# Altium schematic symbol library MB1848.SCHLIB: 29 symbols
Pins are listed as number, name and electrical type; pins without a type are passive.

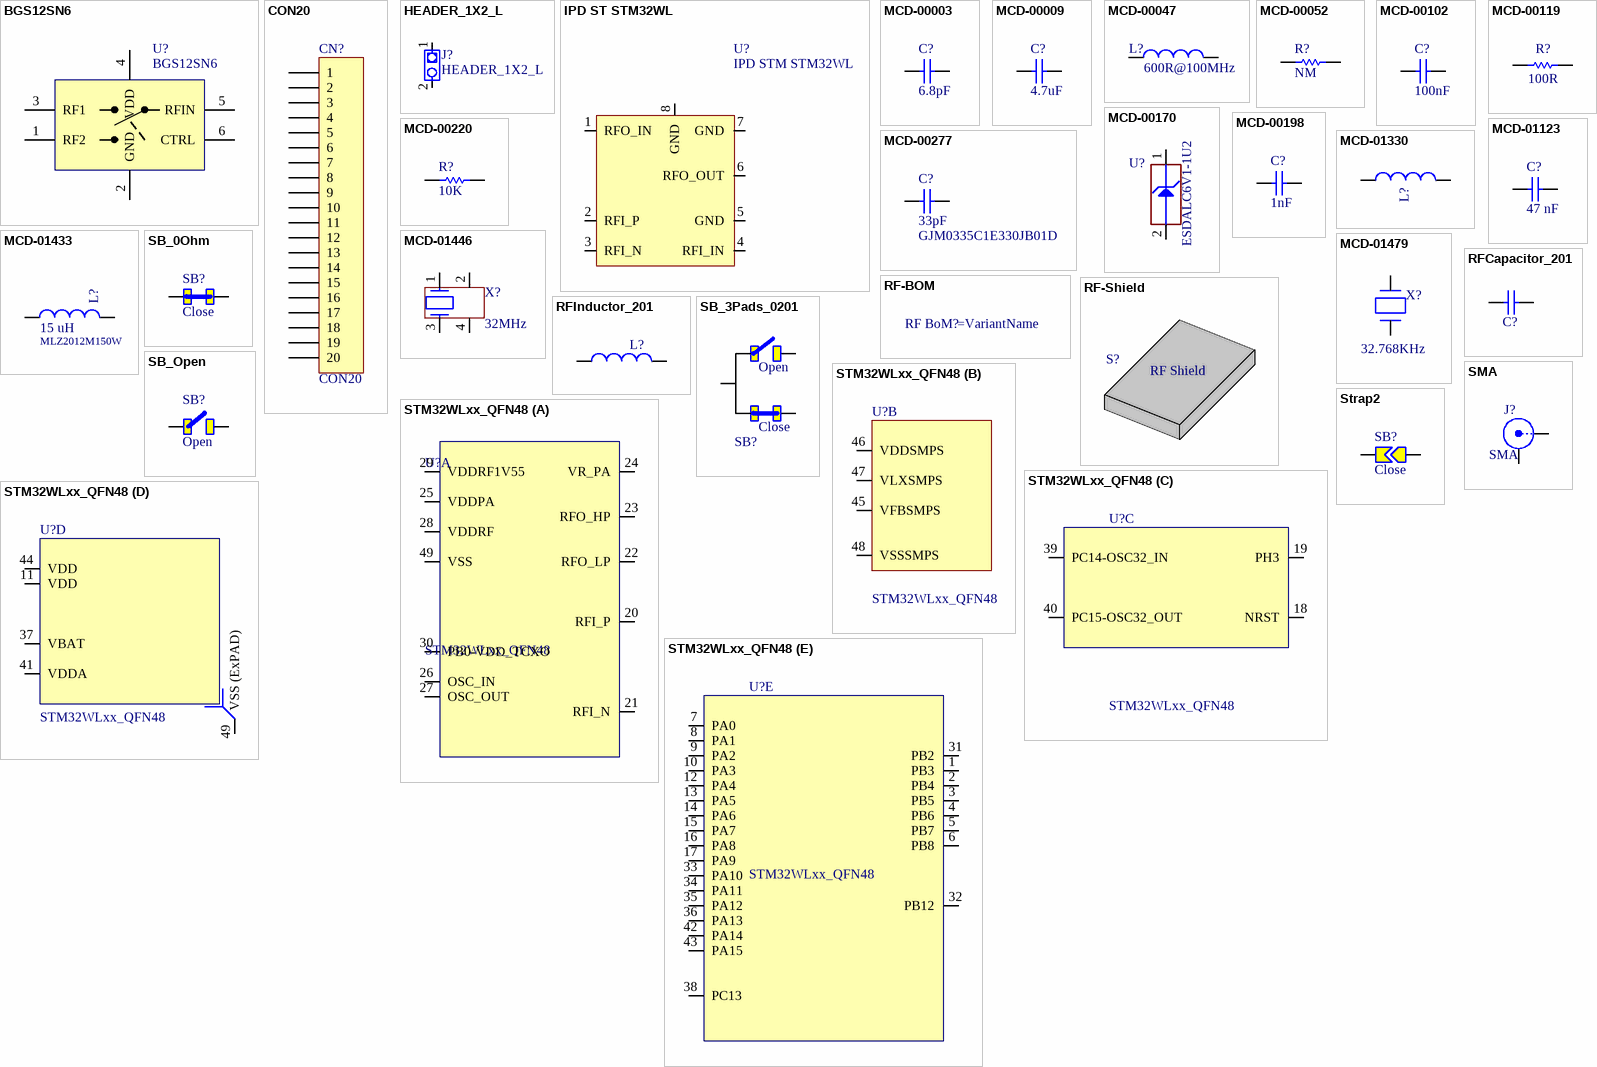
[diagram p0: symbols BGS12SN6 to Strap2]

## BGS12SN6
designator U?
DC switch - Ultra-Low  SPDT analog switch; Manufacturer: INFINEON
footprint SON40P70X40-6N (SON, 6-Leads, Body 1.10x0.70mm, Pitch 0.40mm)
footprint TSNP-6-2 (TSNP-6-2; Body 1.1 x 0.7 mm (LxW typ))
pins: 1 RF2, 2 GND, 3 RF1, 4 VDD, 5 RFIN, 6 CTRL

## CON20
designator CN?
Connector right-angle, pitch 2.54mm, 20 contacts; Manufacturer: SAMTEC; Manufacturer_Part_Number: TSW-120-07-L-S
footprint CO_SAMTEC_TSW-120-07-x-S (Header, 20-Leads, 50.80x2.54x10.80mm, Pitch 2.54mm)
pins: 1, 2, 3, 4, 5, 6, 7, 8, 9, 10, 11, 12, 13, 14, 15, 16, 17, 18, 19, 20

## HEADER_1X2_L
designator J?
Manufacturer: MOLEX
footprint Header F 1x2x2.54 TH V (1x2x2.54 Header TH V Female)
footprint Header M 1x2x2.54 TH V (1x2x2.54 Header TH V Male)
footprint Header F 1x2x2.00 TH V (1x2x2.00 Header TH V Male height=5.5mm)
footprint Header F 1x2x2.00 TH V with Jumper (1x2x2.00 Header TH V Male height=5.5mm)
footprint Header NF 1x2x2.54 TH (1x2x2.54 Header TH Not Fitted)
footprint CO_MOLEX_22-03-2021
pins: 1, 2

## IPD ST STM32WL
designator U?, comment IPD STM STM32WL
Manufacturer: STMICROELECTRONICS
footprint IPD STM (IPD STM STM32WL, Body 2.20 x 1.90 x 0.710 mm (LxWxH max))
pins: 1 RFO_IN, 2 RFI_P, 3 RFI_N, 4 RFI_IN, 5 GND (power), 6 RFO_OUT, 7 GND, 8 GND

## MCD-00003
designator C?, comment value 6.8pF  (hidden comment: Capacitor)
Capacitor, MLCC, 6.8pF, 50V, NPO, +-0.1pF, 0402, T=0.5mm; Manufacturer_Part_Number: GRM1555C1H6R8BA01; Manufacturer: MURATA
footprint 0402
pins: 1, 2

## MCD-00009
designator C?  value 4.7uF
Capacitor, MLCC, 4.7uF, 16V, X5R, 10%, 0603, T=0.8mm; Manufacturer_Part_Number: CC0603KRX5R7BB475; Manufacturer: YAGEO
footprint CAPC1608X09N (Chip Capacitor, 2-Leads, Body 1.60x0.80x0.90mm (0603))
pins: 1, 2

## MCD-00047
designator L?  value 600R@100MHz
SMD Chip ferrite bead, 600R@100MHz +/-25%, 350mA, 500mohm DC, 0603, T=0.8mm; Manufacturer_Part_Number: BK1608HS601-T; Manufacturer: Taiyo Yuden
footprint INDC1608X95N (Chip Inductor, 2-Leads, Body 1.75x0.95x0.95mm (0603))
pins: 1, 2

## MCD-00052
designator R?, comment value NM  (hidden comment: Resistor)
Resistor,0R,0402,5%,1/16W; Internal_Part_Number: MCD-00052; Manufacturer_Part_Number: RC0402JR-070RL; Manufacturer: YAGEO; Provided_By: SUBCO; Initial_Board_Reference: MB1274
footprint R0402
pins: 1, 2

## MCD-00102
designator C?  value 100nF
Capacitor, MLCC, 100nF, 16V, X7R, 10%, 0402, T=0,5mm; Manufacturer_Part_Number: CC0402KRX7R7BB104; Manufacturer: YAGEO
footprint CAPC1005X06N
pins: 1, 2

## MCD-00119
designator R?  value 100R  (hidden comment: MCD-00119)
Thick Film Resistors - SMD 1/20watt 100ohms 5% 200ppm; Manufacturer_Part_Number: CRCW0201100RJNED; Manufacturer: Vishay / Dale
footprint RESC1005X04N (Chip Resistor, 2-Leads, Body 1.00x0.50mm (0402))
footprint 0201
pins: 1, 2

## MCD-00170
designator U?  Manufacturer_Part_Number: ESDALC6V1-1U2
ESD protection 6V1; Manufacturer: STMICROELECTRONICS
footprint DIOM0603X03N (Molded Diode, 2-Leads, Body 0.60x0.30mm)
pins: 1 IO1, 2 GND

## MCD-00198
designator C?  value 1nF  (hidden comment: MCD-00198)
Multilayer ceramic capacitors X7R ±10%, 50V; Manufacturer_Part_Number: GRM033R71H102KA12D; Manufacturer: MURATA
footprint CAPC1005X06N
footprint 0201
pins: 1, 2

## MCD-00220
designator R?  value 10K
Resistor,10K,0603,1%,1/10W; Manufacturer_Part_Number: RC0603FR-0710KL; Manufacturer: YAGEO
footprint RESC1608X05N (Chip Resistor, 2-Leads, Body 1.60x0.80mm (0603))
pins: 1, 2

## MCD-00277
designator C?  value 33pF  Manufacturer_Part_Number: GJM0335C1E330JB01D
Multilayer Ceramic Capacitors MLCC - SMD/SMT 0201 33pF 25volts C0G 5%; Manufacturer: MURATA
footprint 0402
footprint 0201
pins: 1, 2

## MCD-01123
designator C?  value 47 nF
Capacitor, MLCC,47nF, 16V, X7R, 10%, 0402, T=0.5mm; Manufacturer_Part_Number: GCM155R71E473KA55; Manufacturer: MURATA
footprint 0402
pins: 1, 2

## MCD-01330
designator L?  (value not drawn)
Inductor, 47nH, +-0.1nH, 140mA, 0402; Value: NC
footprint IND_MURATA_LQW15A (Inductor 2-Leads,Body 1.10x0.70x0.60mm(max))
pins: 1, 2

## MCD-01433
designator L?  value 15 uH  Manufacturer_Part_Number: MLZ2012M150W
MLZ2012 Multilayer Shielded Inductor 15 uH, ±5%; Manufacturer: TDK
footprint INDC2012X13N (Chip Inductor, 2-Leads, Body 2.0x1.2x1.3 (0805))
pins: 1, 2

## MCD-01446
designator X?  value 32MHz
Crystal 32 MHz, 8pF, -+10 PPM, R=60Ω, SMD; Manufacturer_Part_Number: NX2016SA 32MHz EXS00A-CS06465; Manufacturer: NDK
footprint OSC_NDK_NX2016SA (Crystal, 4-Leads, Body 2.10x1.61x0.50mm (max), Pitch 1.35x1.05mm)
signal-integrity model Guessed Model (IC Model Details Guessed by Setup Helper)
pins: 1, 2, 3, 4

## MCD-01479
designator X?, comment value 32.768KHz  (hidden comment: XTAL_2_PINS)
Crystal 32.768kHz, 6pF, -+20PPM, R=80K, SMD; Manufacturer_Part_Number: NX2012SA 32.768KHz EXS00A-MU00527; Manufacturer: NDK
footprint OSC_NDK_NX2012SA (Crystal, 2-Leads, Body 2.05x1.20x0.55mm (Tol:-/+0.05))
pins: 1 X1, 2 X2

## RF-BOM
designator RF BoM?  (value not drawn)  (mechanical)

## RF-Shield
designator S?  (value not drawn)  (mechanical)
RF Shield Frame + Cover without apertures; Manufacturer: Masach Tech; Manufacturer_Part_Number: MS409-10

## RFCapacitor_201
designator C?  (value not drawn)
RF Capacitor High-Q, 0201; Value: NC
footprint 0201
footprint rlc_201_smd
pins: 1, 2

## RFInductor_201
designator L?, comment Ferrite  (value not drawn)
Thick Film Resistor ±5%, 1/20W; Manufacturer_Part_Number: CRCW02010000Z0ED; Manufacturer: Vishay/Dale; Part_Type: Inductor; Value: 0R
footprint 0201
footprint rlc_201_smd
pins: 1, 2

## SB_0Ohm
designator SB?, comment Close
Solder Bridge 0R [0402] (Populated with 0 Ohm); Manufacturer: Vishay / Dale; Manufacturer_Part_Number: RCS04020000Z0ED; VALUE: 0
footprint SB_0402 (Souder Bridge [0402])
signal-integrity model Guessed Model (IC Model Details Guessed by Setup Helper)
pins: 1, 2

## SB_3Pads_0201
designator SB?, comment SB_3Pads  (value not drawn)
Solder Bridge
footprint SB3PADS_0201 (Solder Bridge 0 Ohm (0201))
pins: 1, 2, 3

## SB_Open
designator SB?, comment Open
Solder Bridge Open [0402] (Unpopulated)
footprint SB_0402 (Souder Bridge [0402])
signal-integrity model Guessed Model (IC Model Details Guessed by Setup Helper)
pins: 1, 2

## SMA
designator J?
SMA Straight Connector; Manufacturer: Johnson / Cinch Connectivity Solutions; Manufacturer_Part_Number: 142-0701-841
footprint SMA_end_launch_1.0mm_9.52mm (SMA end launch for 1.0mm PCB thickness; 9.52mm)
pins: 1 Signal "RF signal", 2 GND "Ground signal"

## STM32WLxx_QFN48
designator U?
STM32WL ARM MCU Multiprotocol LPWAN 32-bit Arm Cortex-M4 MCUs LoRa (G)FSK-MSK BPSK; Manufacturer_Part_Number: STM32WLE5CC; Manufacturer: STMicroelectronics
footprint STM32WLxx_QFN48 (QFN48 7x7x0.55mm pitch 0.5mm)
part A pins: 20 RFI_P, 21 RFI_N, 22 RFO_LP, 23 RFO_HP, 24 VR_PA, 25 VDDPA, 26 OSC_IN, 27 OSC_OUT, 28 VDDRF, 29 VDDRF1V55, 30 PB0-VDD_TCXO, 49 VSS
part B pins: 45 VFBSMPS, 46 VDDSMPS, 47 VLXSMPS, 48 VSSSMPS
part C pins: 18 NRST, 19 PH3, 39 PC14-OSC32_IN, 40 PC15-OSC32_OUT
part D pins: 11 VDD, 37 VBAT, 41 VDDA, 44 VDD, 49 VSS (ExPAD)
part E pins: 1 PB3, 2 PB4, 3 PB5, 4 PB6, 5 PB7, 6 PB8, 7 PA0, 8 PA1, 9 PA2, 10 PA3, 12 PA4, 13 PA5, 14 PA6, 15 PA7, 16 PA8, 17 PA9, 31 PB2, 32 PB12, 33 PA10, 34 PA11, 35 PA12, 36 PA13, 38 PC13, 42 PA14, 43 PA15

## Strap2
designator SB?, comment Close
Solder Jumper - Close; Manufacturer: Vishay / Dale; Manufacturer_Part_Number: RCS04020000Z0ED
footprint SB
footprint GC_0402 (Grain de café format 0402)
footprint SB-LARGE
pins: 1, 2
